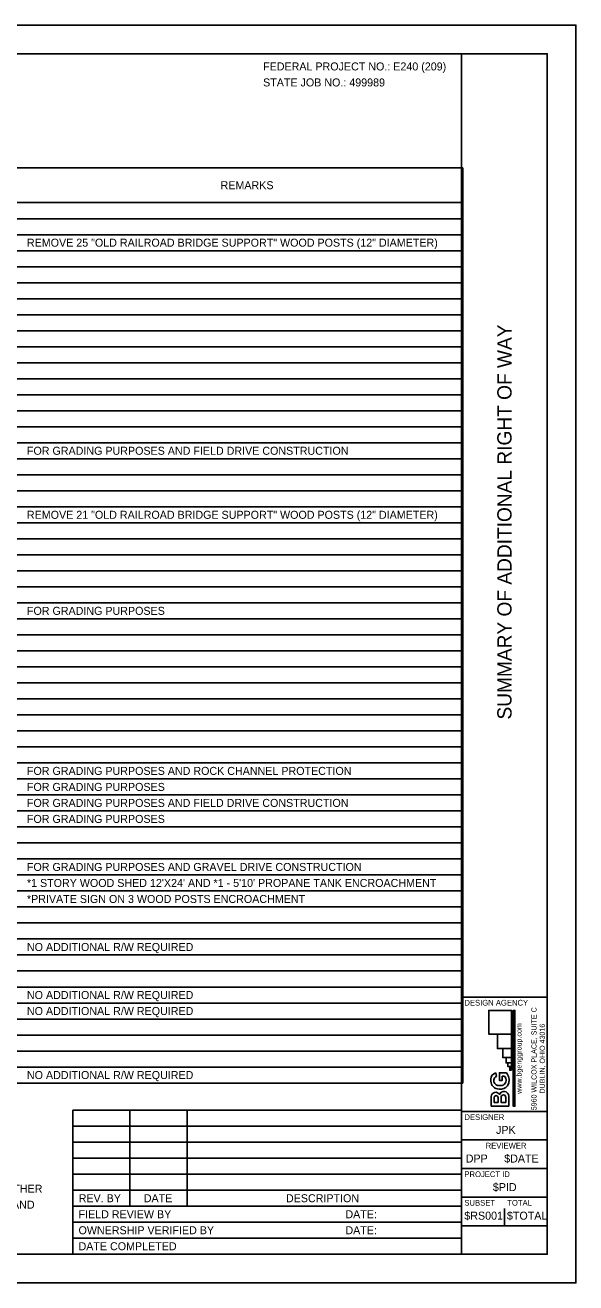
# Model space of a CAD drawing. Extents: x 0 to 34, y 0 to 22.
# Drawn here: x 24.36 to 34, y 0 to 22 of the extents above; entities that cross this region are included whole.
import ezdxf

# ---------------------------------------------------------------- set-up
doc = ezdxf.new("R2010")
doc.units = 0
for name, color, linetype in [('SC_Scratch1', 7, 'Continuous'), ('SH_Border', 7, 'Continuous'), ('SH_Cut_Line', 7, 'Continuous'), ('SH_Data', 7, 'Continuous'), ('SH_Text', 7, 'Continuous')]:
    doc.layers.add(name, color=color, linetype=linetype)

msp = doc.modelspace()

# ---------------------------------------------------------------- linework, layer by layer
at = {"layer": 'SC_Scratch1'}
msp.add_lwpolyline([(31.998, 5), (33.498, 5), (33.498, 3), (31.998, 3)], close=True, dxfattribs=at)
at = {"layer": 'SH_Border'}
for p, q in [((32, 0.5), (32, 21.5)), ((32, 5), (33.5, 5)), ((32, 3), (33.5, 3)), ((32, 2.5), (33.5, 2.5)), ((32, 2), (33.5, 2)), ((32, 1.5), (33.5, 1.5)), ((32, 1), (33.5, 1))]:
    msp.add_line(p, q, dxfattribs=at)
msp.add_lwpolyline([(1.5, 21.5), (33.5, 21.5), (33.5, 0.5), (1.5, 0.5)], close=True, dxfattribs=at)
at = {"layer": 'SH_Cut_Line'}
msp.add_lwpolyline([(0, 0), (34, 0), (34, 22), (0, 22)], close=True, dxfattribs=at)
at = {"layer": 'SH_Data'}
for p, q in [((32.875, 4.352), (32.875, 4.764)), ((32.875, 4.099), (32.875, 4.352)), ((32.75, 4), (32.75, 4)), ((32.875, 3.941), (32.875, 4.099)), ((32.875, 3.847), (32.875, 3.941)), ((32.875, 3.783), (32.875, 3.847)), ((32.875, 3.752), (32.875, 3.783)), ((32.875, 3.72), (32.875, 3.752)), ((32.514, 3.565), (32.514, 3.528)), ((32.514, 3.528), (32.514, 3.565)), ((32.566, 3.551), (32.566, 3.536)), ((32.566, 3.551), (32.566, 3.536)), ((32.613, 3.61), (32.6, 3.671)), ((32.6, 3.671), (32.613, 3.61)), ((32.713, 3.613), (32.753, 3.613)), ((32.697, 3.452), (32.653, 3.451)), ((32.653, 3.451), (32.697, 3.452)), ((32.698, 3.39), (32.657, 3.389)), ((32.698, 3.39), (32.657, 3.389)), ((32.519, 3.093), (32.519, 3.257)), ((32.57, 3.155), (32.57, 3.239)), ((32.692, 3.155), (32.692, 3.245)), ((32.75, 1), (32.75, 1.3))]:
    msp.add_line(p, q, dxfattribs=at)
for points in [[(32.475, 4.352), (32.475, 4.764), (32.875, 4.764), (32.875, 4.352)], [(32.904, 3.088), (32.935, 3.088), (32.935, 4.764), (32.904, 4.764)], [(32.904, 4.764), (32.935, 4.764), (32.935, 3.088), (32.904, 3.088)], [(32.628, 4.099), (32.628, 4.352), (32.875, 4.352), (32.875, 4.099)], [(32.72, 3.941), (32.72, 4.099), (32.875, 4.099), (32.875, 3.941)], [(32.875, 3.941), (32.875, 3.847), (32.78, 3.847), (32.78, 3.941)], [(32.812, 3.783), (32.812, 3.847), (32.875, 3.847), (32.875, 3.783)], [(32.842, 3.752), (32.842, 3.783), (32.875, 3.783), (32.875, 3.752)], [(32.875, 3.72), (32.842, 3.72), (32.842, 3.752), (32.875, 3.752)]]:
    msp.add_lwpolyline(points, close=True, dxfattribs=at)
for points in [[(32.875, 4.764), (32.475, 4.764), (32.475, 4.352), (32.875, 4.352)], [(32.875, 4.352), (32.628, 4.352), (32.628, 4.099), (32.875, 4.099)], [(32.875, 4.099), (32.72, 4.099), (32.72, 3.941), (32.875, 3.941)], [(32.875, 3.941), (32.78, 3.941), (32.78, 3.847), (32.875, 3.847)], [(32.875, 3.847), (32.812, 3.847), (32.812, 3.783), (32.875, 3.783)], [(32.875, 3.783), (32.842, 3.783), (32.842, 3.752), (32.875, 3.752)], [(32.875, 3.752), (32.842, 3.752), (32.842, 3.72), (32.875, 3.72)], [(32.713, 3.613), (32.713, 3.541), (32.662, 3.541), (32.662, 3.675), (32.784, 3.675)], [(32.753, 3.613), (32.713, 3.613), (32.713, 3.541), (32.662, 3.541), (32.662, 3.675), (32.784, 3.675)], [(32.519, 3.093), (32.825, 3.093), (32.825, 3.266)], [(32.825, 3.266), (32.825, 3.093), (32.519, 3.093), (32.519, 3.257)], [(32.57, 3.155), (32.64, 3.155), (32.64, 3.239)], [(32.57, 3.239), (32.57, 3.155), (32.64, 3.155), (32.64, 3.239)], [(32.692, 3.155), (32.774, 3.155), (32.774, 3.245)], [(32.692, 3.245), (32.692, 3.155), (32.774, 3.155), (32.774, 3.245)]]:
    msp.add_lwpolyline(points, dxfattribs=at)
for centre, radius, start, end in [((32.622, 3.565), 0.109, 101.8306, 180), ((32.622, 3.565), 0.109, 101.8306, 180), ((32.653, 3.528), 0.139, 180, 271.4276), ((32.653, 3.528), 0.139, 180, 271.4276), ((32.625, 3.552), 0.0591, 101.8306, 180.9132), ((32.625, 3.552), 0.0591, 101.8306, 180.9132), ((32.651, 3.536), 0.0852, 180, 271.4276), ((32.651, 3.536), 0.0852, 180, 271.4276), ((32.683, 3.545), 0.0981, 315.8822, 44.1178), ((32.683, 3.545), 0.0981, 315.8822, 44.1178), ((32.626, 3.543), 0.206, 344.319, 39.7523), ((32.626, 3.543), 0.206, 344.319, 39.7523), ((32.595, 3.257), 0.0759, 27.219, 180), ((32.595, 3.257), 0.0759, 27.219, 180), ((32.742, 3.266), 0.0837, 360, 162.1627), ((32.742, 3.266), 0.0837, 360, 162.1627), ((32.695, 3.534), 0.0816, 271.4276, 315.8822), ((32.695, 3.534), 0.0816, 271.4276, 315.8822), ((32.695, 3.524), 0.134, 271.4276, 344.319), ((32.695, 3.524), 0.134, 271.4276, 344.319), ((32.605, 3.239), 0.0353, 0, 180), ((32.605, 3.239), 0.0353, 0, 180), ((32.733, 3.245), 0.0414, 0, 180), ((32.733, 3.245), 0.0414, 0, 180)]:
    msp.add_arc(centre, radius, start, end, dxfattribs=at)
at = {"layer": 'SH_Text'}
for p, q in [((1.5, 19.505), (32.02, 19.505)), ((32.02, 19.505), (32.02, 3.495)), ((1.5, 18.895), (32.02, 18.895)), ((16.142, 18.615), (32.02, 18.615)), ((1.5, 18.335), (32.02, 18.335)), ((16.142, 18.055), (32.02, 18.055)), ((1.5, 17.775), (32.02, 17.775)), ((1.5, 17.495), (32.02, 17.495)), ((12.041, 17.215), (32.02, 17.215)), ((12.041, 16.935), (32.02, 16.935)), ((12.041, 16.655), (32.02, 16.655)), ((12.041, 16.375), (32.02, 16.375)), ((12.041, 16.095), (32.02, 16.095)), ((12.041, 15.815), (32.02, 15.815)), ((1.5, 15.535), (32.02, 15.535)), ((1.5, 15.255), (32.02, 15.255)), ((1.5, 14.975), (32.02, 14.975)), ((1.5, 14.695), (32.02, 14.695)), ((1.5, 14.415), (32.02, 14.415)), ((1.5, 14.135), (32.02, 14.135)), ((1.5, 13.855), (32.02, 13.855)), ((12.041, 13.575), (32.02, 13.575)), ((12.041, 13.295), (32.02, 13.295)), ((12.041, 13.015), (32.02, 13.015)), ((12.041, 12.735), (32.02, 12.735)), ((1.5, 12.455), (32.02, 12.455)), ((1.5, 12.175), (32.02, 12.175)), ((1.5, 11.895), (32.02, 11.895)), ((1.5, 11.615), (32.02, 11.615)), ((1.5, 11.335), (32.02, 11.335)), ((1.5, 11.055), (32.02, 11.055)), ((16.142, 10.775), (32.02, 10.775)), ((1.5, 10.495), (32.02, 10.495)), ((12.041, 10.215), (32.02, 10.215)), ((1.5, 9.935), (32.02, 9.935)), ((1.5, 9.655), (32.02, 9.655)), ((1.5, 9.375), (32.02, 9.375)), ((1.5, 9.095), (32.02, 9.095)), ((9.604, 8.815), (32.02, 8.815)), ((1.5, 8.535), (32.02, 8.535)), ((1.5, 8.255), (32.02, 8.255)), ((1.5, 7.975), (32.02, 7.975)), ((1.5, 7.695), (32.02, 7.695)), ((1.5, 7.415), (32.02, 7.415)), ((1.5, 7.135), (32.02, 7.135)), ((1.5, 6.855), (32.02, 6.855)), ((1.5, 6.575), (32.02, 6.575)), ((1.5, 6.295), (32.02, 6.295)), ((1.5, 6.015), (32.02, 6.015)), ((1.5, 5.735), (32.02, 5.735)), ((1.5, 5.455), (32.02, 5.455)), ((1.5, 5.175), (32.02, 5.175)), ((9.604, 4.895), (32.02, 4.895)), ((1.5, 4.615), (32.02, 4.615)), ((1.5, 4.335), (32.02, 4.335)), ((1.5, 4.055), (32.02, 4.055)), ((1.5, 3.775), (32.02, 3.775)), ((1.5, 3.495), (32.02, 3.495)), ((25.197, 3.02), (25.197, 0.5)), ((25.197, 3.02), (32, 3.02)), ((26.197, 3.02), (26.197, 1.34)), ((27.197, 3.02), (27.197, 1.34)), ((25.197, 2.74), (32, 2.74)), ((25.197, 2.46), (32, 2.46)), ((25.197, 2.18), (32, 2.18)), ((25.197, 1.9), (32, 1.9)), ((25.197, 1.62), (32, 1.62)), ((25.197, 1.34), (32, 1.34)), ((25.197, 1.06), (32, 1.06)), ((25.197, 0.78), (32, 0.78)), ((32, 0.5), (32, 0.5))]:
    msp.add_line(p, q, dxfattribs=at)

# ---------------------------------------------------------------- texts
at = {"layer": 'SH_Data'}
for s, height, p in [('SUMMARY OF ADDITIONAL RIGHT OF WAY', 0.25, (32.875, 9.854)), ('5960 WILCOX PLACE, SUITE C', 0.09, (33.312, 3.018)), ('www.bgenggroup.com', 0.09, (33.049, 3.306)), ('DUBLIN, OHIO 43016', 0.09, (33.457, 3.311))]:
    msp.add_text(s, height=height, rotation=90, dxfattribs=at).set_placement(p)
for s, height, p in [('DESIGN AGENCY', 0.1, (32.05, 4.85)), ('DESIGNER', 0.1, (32.05, 2.85)), ('JPK', 0.14, (32.603, 2.605)), ('REVIEWER', 0.1, (32.422, 2.35)), ('DPP', 0.14, (32.073, 2.105)), ('$DATE', 0.14, (32.746, 2.105)), ('PROJECT ID', 0.1, (32.05, 1.85)), ('SUBSET', 0.1, (32.05, 1.35)), ('TOTAL', 0.1, (32.8, 1.35)), ('$RS001', 0.14, (32.048, 1.105)), ('$TOTAL', 0.14, (32.794, 1.105))]:
    msp.add_text(s, height=height, dxfattribs=at).set_placement(p)
at = {"layer": 'SH_Text'}
for s, p in [('FEDERAL PROJECT NO.: E240 (209) ', (28.527, 21.208)), ('STATE JOB NO.: 499989', (28.527, 20.928)), ('REMARKS', (27.783, 19.13)), ('REMOVE 25 "OLD RAILROAD BRIDGE SUPPORT" WOOD POSTS (12" DIAMETER)', (24.394, 18.125)), ('FOR GRADING PURPOSES AND FIELD DRIVE CONSTRUCTION', (24.394, 14.485)), ('REMOVE 21 "OLD RAILROAD BRIDGE SUPPORT" WOOD POSTS (12" DIAMETER)', (24.394, 13.365)), ('REMOVE 21 "OLD RAILROAD BRIDGE SUPPORT" WOOD POSTS (12" DIAMETER)', (24.394, 13.365)), ('FOR GRADING PURPOSES', (24.394, 11.685)), ('FOR GRADING PURPOSES AND ROCK CHANNEL PROTECTION', (24.394, 8.885)), ('FOR GRADING PURPOSES', (24.394, 8.605)), ('FOR GRADING PURPOSES AND FIELD DRIVE CONSTRUCTION', (24.394, 8.325)), ('FOR GRADING PURPOSES', (24.394, 8.045)), ('FOR GRADING PURPOSES AND GRAVEL DRIVE CONSTRUCTION', (24.394, 7.205)), ("*1 STORY WOOD SHED 12'X24' AND *1 - 5'10' PROPANE TANK ENCROACHMENT", (24.394, 6.925)), ('*PRIVATE SIGN ON 3 WOOD POSTS ENCROACHMENT', (24.394, 6.645)), ('NO ADDITIONAL R/W REQUIRED', (24.394, 5.805)), ('NO ADDITIONAL R/W REQUIRED', (24.394, 4.965)), ('NO ADDITIONAL R/W REQUIRED', (24.394, 4.685)), ('NO ADDITIONAL R/W REQUIRED', (24.394, 3.565)), ('ANY RIGHT OF WAY ACQUIRED IN THE NAME OF ANOTHER ', (19.278, 1.577)), ('REV. BY', (25.3, 1.41)), ('DATE', (26.439, 1.41)), ('DESCRIPTION', (28.927, 1.41)), ('$PID', (32.547, 1.605)), ('AGENCY WILL CONTAIN THE "V" PARCEL IDENTIFIER AND ', (19.278, 1.297)), ('FIELD REVIEW BY', (25.297, 1.13)), ('DATE:', (29.967, 1.13)), ('OWNERSHIP VERIFIED BY', (25.297, 0.85)), ('DATE:', (29.967, 0.85)), ('DATE COMPLETED', (25.297, 0.57))]:
    msp.add_text(s, height=0.14, dxfattribs=at).set_placement(p)

doc.saveas('drawing.dxf')
